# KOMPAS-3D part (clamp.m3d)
File: created 17.03.2016 12:24:08, last saved 18.09.2016 21:49:20.
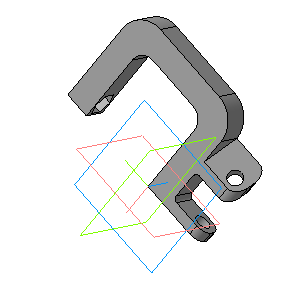
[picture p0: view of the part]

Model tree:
1. Эскиз:1
2. Операция выдавливания:1
     Расстояние 1 = 12
3. Эскиз:2
4. Вырезать элемент выдавливания:1
     Расстояние 1 = 20
5. Эскиз:3
6. Вырезать элемент выдавливания:2
     Расстояние 1 = 5
7. Скругление:1
     Радиус = 7
8. Скругление:2
     Радиус = 7
9. Скругление:3
     Радиус = 13
10. Эскиз:4
11. Операция выдавливания:2
     Расстояние 1 = 20
12. Эскиз:5
13. Вырезать элемент выдавливания:3
     Расстояние 1 = 10
14. Эскиз:6
15. Вырезать элемент выдавливания:4
     Расстояние 1 = 10
16. Скругление:4
     Радиус = 5
17. Скругление:6
     Радиус = 2
18. Скругление:7
     Радиус = 2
